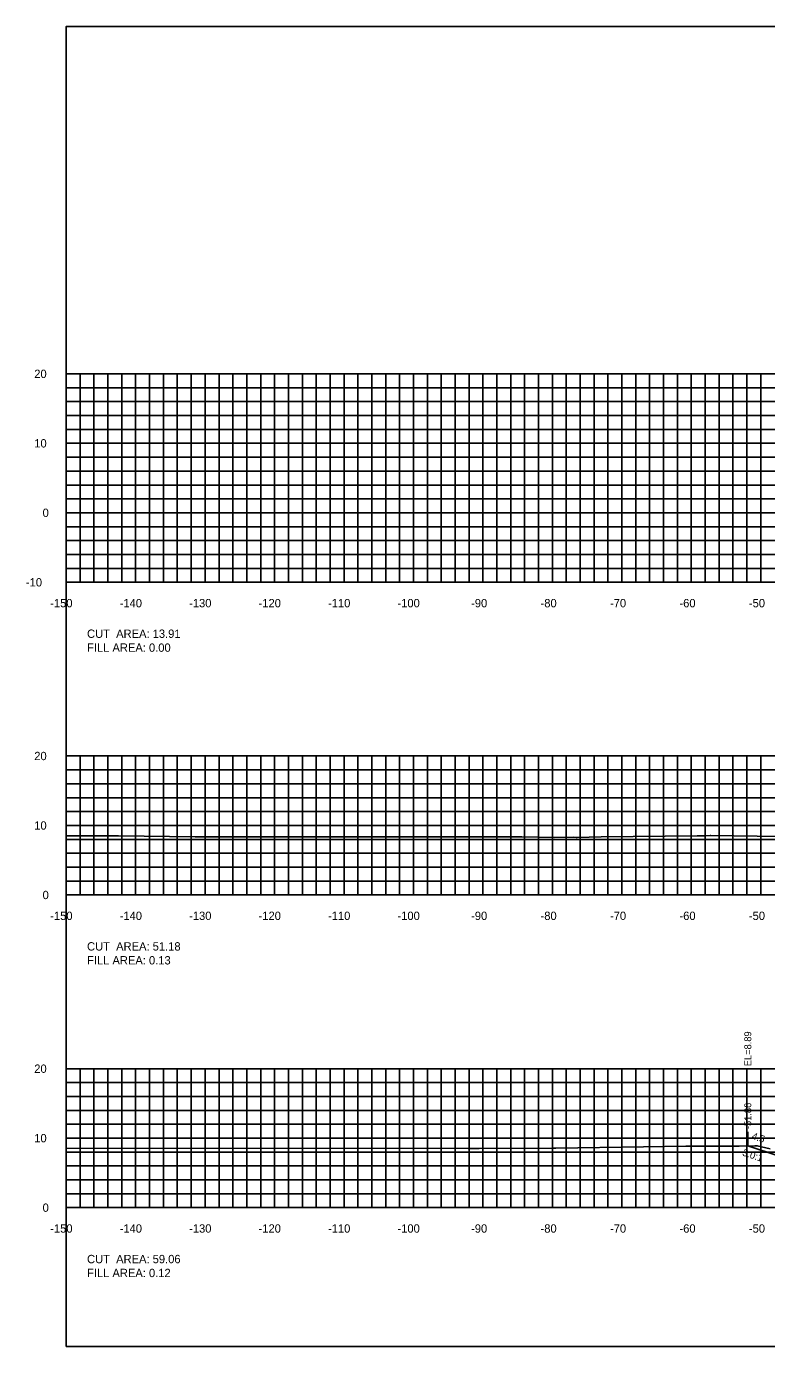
# Model space of a CAD drawing. Extents: x 1800876 to 1802446, y 250079 to 250269.
# Drawn here: x 1802135.3 to 1802241.8, y 250079.4 to 250269.4 of the extents above; entities that cross this region are included whole.
import ezdxf

# ---------------------------------------------------------------- set-up
doc = ezdxf.new("R2010")
doc.units = 0
for name, color, linetype in [('10', 7, 'Continuous'), ('3', 7, 'Continuous'), ('31', 7, 'Continuous'), ('4', 7, 'Continuous'), ('60', 7, 'Continuous'), ('ANNO-TXT', 7, 'Continuous'), ('CL-CNST', 7, 'Continuous'), ('Level 62', 7, 'Continuous'), ('M-ROADS', 7, 'Continuous')]:
    doc.layers.add(name, color=color, linetype=linetype)

msp = doc.modelspace()

# ---------------------------------------------------------------- linework, layer by layer
msp.add_line((1802239.14, 250108.32), (1802239.14, 250110.32))
msp.add_lwpolyline([(1802141, 250079.43), (1802441, 250079.43), (1802441, 250269.43), (1802141, 250269.43)], close=True)
at = {"layer": '60'}
for p, q in [((1802140.94, 250219.43), (1802141, 250219.43)), ((1802141, 250189.43), (1802141, 250219.43)), ((1802140.94, 250209.43), (1802141, 250209.43)), ((1802140.94, 250199.43), (1802141, 250199.43)), ((1802140.94, 250189.43), (1802141, 250189.43)), ((1802141, 250189.43), (1802441, 250189.43)), ((1802141, 250189.37), (1802141, 250189.43)), ((1802151, 250189.37), (1802151, 250189.43)), ((1802161, 250189.37), (1802161, 250189.43)), ((1802171, 250189.37), (1802171, 250189.43)), ((1802181, 250189.37), (1802181, 250189.43)), ((1802191, 250189.37), (1802191, 250189.43)), ((1802201, 250189.37), (1802201, 250189.43)), ((1802211, 250189.37), (1802211, 250189.43)), ((1802221, 250189.37), (1802221, 250189.43)), ((1802231, 250189.37), (1802231, 250189.43)), ((1802241, 250189.37), (1802241, 250189.43)), ((1802140.94, 250164.43), (1802141, 250164.43)), ((1802141, 250144.43), (1802141, 250164.43)), ((1802140.94, 250154.43), (1802141, 250154.43)), ((1802140.94, 250144.43), (1802141, 250144.43)), ((1802141, 250144.43), (1802441, 250144.43)), ((1802141, 250144.37), (1802141, 250144.43)), ((1802151, 250144.37), (1802151, 250144.43)), ((1802161, 250144.37), (1802161, 250144.43)), ((1802171, 250144.37), (1802171, 250144.43)), ((1802181, 250144.37), (1802181, 250144.43)), ((1802191, 250144.37), (1802191, 250144.43)), ((1802201, 250144.37), (1802201, 250144.43)), ((1802211, 250144.37), (1802211, 250144.43)), ((1802221, 250144.37), (1802221, 250144.43)), ((1802231, 250144.37), (1802231, 250144.43)), ((1802241, 250144.37), (1802241, 250144.43)), ((1802140.94, 250119.43), (1802141, 250119.43)), ((1802141, 250099.43), (1802141, 250119.43)), ((1802140.94, 250109.43), (1802141, 250109.43)), ((1802140.94, 250099.43), (1802141, 250099.43)), ((1802141, 250099.43), (1802441, 250099.43)), ((1802141, 250099.37), (1802141, 250099.43)), ((1802151, 250099.37), (1802151, 250099.43)), ((1802161, 250099.37), (1802161, 250099.43)), ((1802171, 250099.37), (1802171, 250099.43)), ((1802181, 250099.37), (1802181, 250099.43)), ((1802191, 250099.37), (1802191, 250099.43)), ((1802201, 250099.37), (1802201, 250099.43)), ((1802211, 250099.37), (1802211, 250099.43)), ((1802221, 250099.37), (1802221, 250099.43)), ((1802231, 250099.37), (1802231, 250099.43)), ((1802241, 250099.37), (1802241, 250099.43))]:
    msp.add_line(p, q, dxfattribs=at)
at = {"layer": 'CL-CNST'}
msp.add_lwpolyline([(1802239.14, 250108.32), (1802243.65, 250106.82)], dxfattribs=at)
at = {"layer": 'Level 62'}
for p, q in [((1802141, 250219.43), (1802441, 250219.43)), ((1802141, 250189.43), (1802141, 250219.43)), ((1802143, 250189.43), (1802143, 250219.43)), ((1802145, 250189.43), (1802145, 250219.43)), ((1802147, 250189.43), (1802147, 250219.43)), ((1802149, 250189.43), (1802149, 250219.43)), ((1802151, 250189.43), (1802151, 250219.43)), ((1802153, 250189.43), (1802153, 250219.43)), ((1802155, 250189.43), (1802155, 250219.43)), ((1802157, 250189.43), (1802157, 250219.43)), ((1802159, 250189.43), (1802159, 250219.43)), ((1802161, 250189.43), (1802161, 250219.43)), ((1802163, 250189.43), (1802163, 250219.43)), ((1802165, 250189.43), (1802165, 250219.43)), ((1802167, 250189.43), (1802167, 250219.43)), ((1802169, 250189.43), (1802169, 250219.43)), ((1802171, 250189.43), (1802171, 250219.43)), ((1802173, 250189.43), (1802173, 250219.43)), ((1802175, 250189.43), (1802175, 250219.43)), ((1802177, 250189.43), (1802177, 250219.43)), ((1802179, 250189.43), (1802179, 250219.43)), ((1802181, 250189.43), (1802181, 250219.43)), ((1802183, 250189.43), (1802183, 250219.43)), ((1802185, 250189.43), (1802185, 250219.43)), ((1802187, 250189.43), (1802187, 250219.43)), ((1802189, 250189.43), (1802189, 250219.43)), ((1802191, 250189.43), (1802191, 250219.43)), ((1802193, 250189.43), (1802193, 250219.43)), ((1802195, 250189.43), (1802195, 250219.43)), ((1802197, 250189.43), (1802197, 250219.43)), ((1802199, 250189.43), (1802199, 250219.43)), ((1802201, 250189.43), (1802201, 250219.43)), ((1802203, 250189.43), (1802203, 250219.43)), ((1802205, 250189.43), (1802205, 250219.43)), ((1802207, 250189.43), (1802207, 250219.43)), ((1802209, 250189.43), (1802209, 250219.43)), ((1802211, 250189.43), (1802211, 250219.43)), ((1802213, 250189.43), (1802213, 250219.43)), ((1802215, 250189.43), (1802215, 250219.43)), ((1802217, 250189.43), (1802217, 250219.43)), ((1802219, 250189.43), (1802219, 250219.43)), ((1802221, 250189.43), (1802221, 250219.43)), ((1802223, 250189.43), (1802223, 250219.43)), ((1802225, 250189.43), (1802225, 250219.43)), ((1802227, 250189.43), (1802227, 250219.43)), ((1802229, 250189.43), (1802229, 250219.43)), ((1802231, 250189.43), (1802231, 250219.43)), ((1802233, 250189.43), (1802233, 250219.43)), ((1802235, 250189.43), (1802235, 250219.43)), ((1802237, 250189.43), (1802237, 250219.43)), ((1802239, 250189.43), (1802239, 250219.43)), ((1802241, 250189.43), (1802241, 250219.43)), ((1802141, 250217.43), (1802441, 250217.43)), ((1802141, 250215.43), (1802441, 250215.43)), ((1802141, 250213.43), (1802441, 250213.43)), ((1802141, 250211.43), (1802441, 250211.43)), ((1802141, 250209.43), (1802441, 250209.43)), ((1802141, 250207.43), (1802441, 250207.43)), ((1802141, 250205.43), (1802441, 250205.43)), ((1802141, 250203.43), (1802441, 250203.43)), ((1802141, 250201.43), (1802441, 250201.43)), ((1802141, 250199.43), (1802441, 250199.43)), ((1802141, 250197.43), (1802441, 250197.43)), ((1802141, 250195.43), (1802441, 250195.43)), ((1802141, 250193.43), (1802441, 250193.43)), ((1802141, 250191.43), (1802441, 250191.43)), ((1802141, 250189.43), (1802441, 250189.43)), ((1802141, 250164.43), (1802441, 250164.43)), ((1802141, 250144.43), (1802141, 250164.43)), ((1802143, 250144.43), (1802143, 250164.43)), ((1802145, 250144.43), (1802145, 250164.43)), ((1802147, 250144.43), (1802147, 250164.43)), ((1802149, 250144.43), (1802149, 250164.43)), ((1802151, 250144.43), (1802151, 250164.43)), ((1802153, 250144.43), (1802153, 250164.43)), ((1802155, 250144.43), (1802155, 250164.43)), ((1802157, 250144.43), (1802157, 250164.43)), ((1802159, 250144.43), (1802159, 250164.43)), ((1802161, 250144.43), (1802161, 250164.43)), ((1802163, 250144.43), (1802163, 250164.43)), ((1802165, 250144.43), (1802165, 250164.43)), ((1802167, 250144.43), (1802167, 250164.43)), ((1802169, 250144.43), (1802169, 250164.43)), ((1802171, 250144.43), (1802171, 250164.43)), ((1802173, 250144.43), (1802173, 250164.43)), ((1802175, 250144.43), (1802175, 250164.43)), ((1802177, 250144.43), (1802177, 250164.43)), ((1802179, 250144.43), (1802179, 250164.43)), ((1802181, 250144.43), (1802181, 250164.43)), ((1802183, 250144.43), (1802183, 250164.43)), ((1802185, 250144.43), (1802185, 250164.43)), ((1802187, 250144.43), (1802187, 250164.43)), ((1802189, 250144.43), (1802189, 250164.43)), ((1802191, 250144.43), (1802191, 250164.43)), ((1802193, 250144.43), (1802193, 250164.43)), ((1802195, 250144.43), (1802195, 250164.43)), ((1802197, 250144.43), (1802197, 250164.43)), ((1802199, 250144.43), (1802199, 250164.43)), ((1802201, 250144.43), (1802201, 250164.43)), ((1802203, 250144.43), (1802203, 250164.43)), ((1802205, 250144.43), (1802205, 250164.43)), ((1802207, 250144.43), (1802207, 250164.43)), ((1802209, 250144.43), (1802209, 250164.43)), ((1802211, 250144.43), (1802211, 250164.43)), ((1802213, 250144.43), (1802213, 250164.43)), ((1802215, 250144.43), (1802215, 250164.43)), ((1802217, 250144.43), (1802217, 250164.43)), ((1802219, 250144.43), (1802219, 250164.43)), ((1802221, 250144.43), (1802221, 250164.43)), ((1802223, 250144.43), (1802223, 250164.43)), ((1802225, 250144.43), (1802225, 250164.43)), ((1802227, 250144.43), (1802227, 250164.43)), ((1802229, 250144.43), (1802229, 250164.43)), ((1802231, 250144.43), (1802231, 250164.43)), ((1802233, 250144.43), (1802233, 250164.43)), ((1802235, 250144.43), (1802235, 250164.43)), ((1802237, 250144.43), (1802237, 250164.43)), ((1802239, 250144.43), (1802239, 250164.43)), ((1802241, 250144.43), (1802241, 250164.43)), ((1802141, 250162.43), (1802441, 250162.43)), ((1802141, 250160.43), (1802441, 250160.43)), ((1802141, 250158.43), (1802441, 250158.43)), ((1802141, 250156.43), (1802441, 250156.43)), ((1802141, 250154.43), (1802441, 250154.43)), ((1802141, 250152.43), (1802441, 250152.43)), ((1802141, 250150.43), (1802441, 250150.43)), ((1802141, 250148.43), (1802441, 250148.43)), ((1802141, 250146.43), (1802441, 250146.43)), ((1802141, 250144.43), (1802441, 250144.43)), ((1802141, 250119.43), (1802441, 250119.43)), ((1802141, 250099.43), (1802141, 250119.43)), ((1802143, 250099.43), (1802143, 250119.43)), ((1802145, 250099.43), (1802145, 250119.43)), ((1802147, 250099.43), (1802147, 250119.43)), ((1802149, 250099.43), (1802149, 250119.43)), ((1802151, 250099.43), (1802151, 250119.43)), ((1802153, 250099.43), (1802153, 250119.43)), ((1802155, 250099.43), (1802155, 250119.43)), ((1802157, 250099.43), (1802157, 250119.43)), ((1802159, 250099.43), (1802159, 250119.43)), ((1802161, 250099.43), (1802161, 250119.43)), ((1802163, 250099.43), (1802163, 250119.43)), ((1802165, 250099.43), (1802165, 250119.43)), ((1802167, 250099.43), (1802167, 250119.43)), ((1802169, 250099.43), (1802169, 250119.43)), ((1802171, 250099.43), (1802171, 250119.43)), ((1802173, 250099.43), (1802173, 250119.43)), ((1802175, 250099.43), (1802175, 250119.43)), ((1802177, 250099.43), (1802177, 250119.43)), ((1802179, 250099.43), (1802179, 250119.43)), ((1802181, 250099.43), (1802181, 250119.43)), ((1802183, 250099.43), (1802183, 250119.43)), ((1802185, 250099.43), (1802185, 250119.43)), ((1802187, 250099.43), (1802187, 250119.43)), ((1802189, 250099.43), (1802189, 250119.43)), ((1802191, 250099.43), (1802191, 250119.43)), ((1802193, 250099.43), (1802193, 250119.43)), ((1802195, 250099.43), (1802195, 250119.43)), ((1802197, 250099.43), (1802197, 250119.43)), ((1802199, 250099.43), (1802199, 250119.43)), ((1802201, 250099.43), (1802201, 250119.43)), ((1802203, 250099.43), (1802203, 250119.43)), ((1802205, 250099.43), (1802205, 250119.43)), ((1802207, 250099.43), (1802207, 250119.43)), ((1802209, 250099.43), (1802209, 250119.43)), ((1802211, 250099.43), (1802211, 250119.43)), ((1802213, 250099.43), (1802213, 250119.43)), ((1802215, 250099.43), (1802215, 250119.43)), ((1802217, 250099.43), (1802217, 250119.43)), ((1802219, 250099.43), (1802219, 250119.43)), ((1802221, 250099.43), (1802221, 250119.43)), ((1802223, 250099.43), (1802223, 250119.43)), ((1802225, 250099.43), (1802225, 250119.43)), ((1802227, 250099.43), (1802227, 250119.43)), ((1802229, 250099.43), (1802229, 250119.43)), ((1802231, 250099.43), (1802231, 250119.43)), ((1802233, 250099.43), (1802233, 250119.43)), ((1802235, 250099.43), (1802235, 250119.43)), ((1802237, 250099.43), (1802237, 250119.43)), ((1802239, 250099.43), (1802239, 250119.43)), ((1802241, 250099.43), (1802241, 250119.43)), ((1802141, 250117.43), (1802441, 250117.43)), ((1802141, 250115.43), (1802441, 250115.43)), ((1802141, 250113.43), (1802441, 250113.43)), ((1802141, 250111.43), (1802441, 250111.43)), ((1802141, 250109.43), (1802441, 250109.43)), ((1802141, 250107.43), (1802441, 250107.43)), ((1802141, 250105.43), (1802441, 250105.43)), ((1802141, 250103.43), (1802441, 250103.43)), ((1802141, 250101.43), (1802441, 250101.43)), ((1802141, 250099.43), (1802441, 250099.43))]:
    msp.add_line(p, q, dxfattribs=at)
at = {"layer": 'M-ROADS'}
for points in [[(1802141, 250152.92), (1802148.53, 250152.92), (1802159.59, 250152.8), (1802159.84, 250152.8), (1802206.59, 250152.82), (1802211.27, 250152.7), (1802214.1, 250152.73), (1802214.45, 250152.72), (1802214.56, 250152.72), (1802218.05, 250152.78), (1802231.87, 250152.95), (1802232.27, 250152.94), (1802232.53, 250152.94), (1802232.86, 250152.95), (1802233.72, 250152.97), (1802233.84, 250152.97), (1802247.14, 250152.8)], [(1802141, 250107.99), (1802198.88, 250107.96), (1802200.45, 250107.92), (1802211.01, 250108.01), (1802211.07, 250108.01), (1802211.48, 250108), (1802224.11, 250108.19), (1802230.24, 250108.26), (1802230.43, 250108.26), (1802237.92, 250108.3), (1802240.15, 250108.34), (1802240.31, 250108.34), (1802240.49, 250108.34), (1802242.37, 250107.89)]]:
    msp.add_lwpolyline(points, dxfattribs=at)

# ---------------------------------------------------------------- texts
msp.add_text('3.0:1', height=1, rotation=341.5648).set_placement((1802238.28, 250106.96))
at = {"layer": '10'}
for s, p in [('-150', (1802138.7, 250185.83)), ('-140', (1802148.7, 250185.83)), ('-130', (1802158.7, 250185.83)), ('-120', (1802168.7, 250185.83)), ('-110', (1802178.7, 250185.83)), ('-100', (1802188.7, 250185.83)), ('-90', (1802199.3, 250185.83)), ('-80', (1802209.3, 250185.83)), ('-70', (1802219.3, 250185.83)), ('-60', (1802229.3, 250185.83)), ('-50', (1802239.3, 250185.83)), ('-150', (1802138.7, 250140.83)), ('-140', (1802148.7, 250140.83)), ('-130', (1802158.7, 250140.83)), ('-120', (1802168.7, 250140.83)), ('-110', (1802178.7, 250140.83)), ('-100', (1802188.7, 250140.83)), ('-90', (1802199.3, 250140.83)), ('-80', (1802209.3, 250140.83)), ('-70', (1802219.3, 250140.83)), ('-60', (1802229.3, 250140.83)), ('-50', (1802239.3, 250140.83)), ('-150', (1802138.7, 250095.83)), ('-140', (1802148.7, 250095.83)), ('-130', (1802158.7, 250095.83)), ('-120', (1802168.7, 250095.83)), ('-110', (1802178.7, 250095.83)), ('-100', (1802188.7, 250095.83)), ('-90', (1802199.3, 250095.83)), ('-80', (1802209.3, 250095.83)), ('-70', (1802219.3, 250095.83)), ('-60', (1802229.3, 250095.83)), ('-50', (1802239.3, 250095.83))]:
    msp.add_text(s, height=1.2, dxfattribs=at).set_placement(p)
at = {"layer": '3'}
for s, p in [('EL=8.89', (1802239.64, 250119.78)), ('-51.86', (1802239.64, 250110.73))]:
    msp.add_text(s, height=1, rotation=90, dxfattribs=at).set_placement(p)
at = {"layer": '31'}
for s, p in [('20', (1802136.4, 250218.83)), ('10', (1802136.4, 250208.83)), ('0', (1802137.6, 250198.83)), ('-10', (1802135.2, 250188.83)), ('20', (1802136.4, 250163.83)), ('10', (1802136.4, 250153.83)), ('0', (1802137.6, 250143.83)), ('20', (1802136.4, 250118.83)), ('10', (1802136.4, 250108.83)), ('0', (1802137.6, 250098.83))]:
    msp.add_text(s, height=1.2, dxfattribs=at).set_placement(p)
at = {"layer": '4'}
msp.add_text('4.5', height=1, rotation=341.5648, dxfattribs=at).set_placement((1802239.64, 250109.34))
at = {"layer": '60'}
for p in [(1802141, 250189.43), (1802141, 250144.43), (1802141, 250099.43)]:
    msp.add_text('-', height=0.0001, dxfattribs=at).set_placement(p)
at = {"layer": 'ANNO-TXT'}
for s, p in [('CUT  AREA: 13.91', (1802144, 250181.43)), ('FILL AREA: 0.00', (1802144, 250179.43)), ('CUT  AREA: 51.18', (1802144, 250136.43)), ('FILL AREA: 0.13', (1802144, 250134.43)), ('CUT  AREA: 59.06', (1802144, 250091.43)), ('FILL AREA: 0.12', (1802144, 250089.43))]:
    msp.add_text(s, height=1.2, dxfattribs=at).set_placement(p)

doc.saveas('drawing.dxf')
